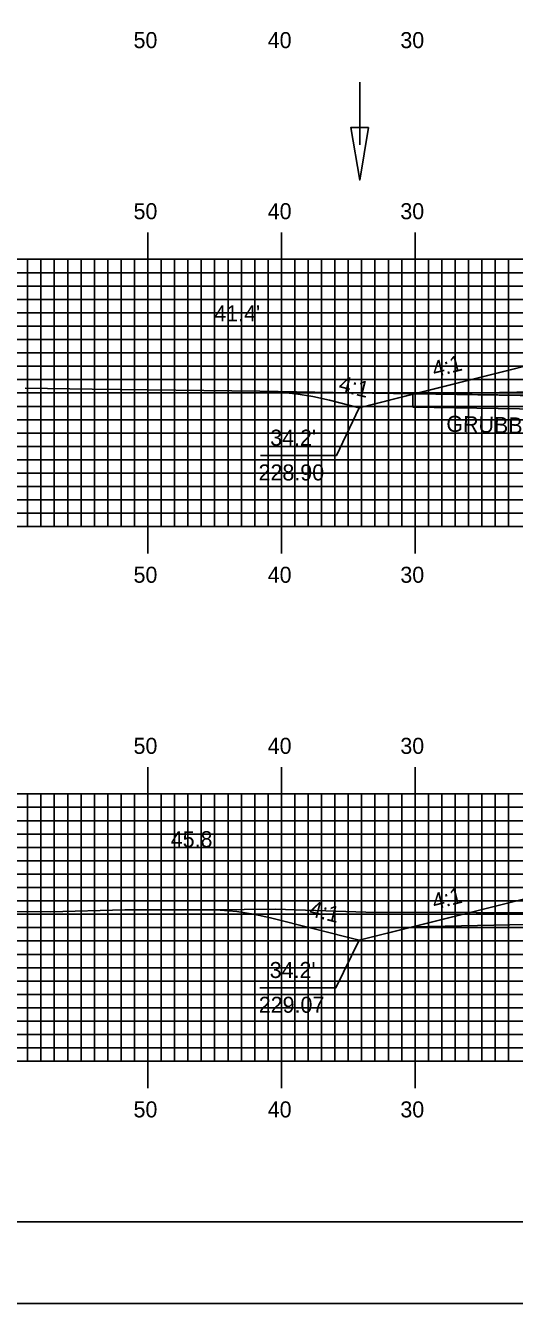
# Model space of a CAD drawing. Extents: x 1803503 to 1803847, y 442591 to 442811.
# Drawn here: x 1803610 to 1803646.6, y 442590.5 to 442686.2 of the extents above; entities that cross this region are included whole.
import ezdxf

# ---------------------------------------------------------------- set-up
doc = ezdxf.new("R2010")
doc.units = 0
for name, color, linetype in [('ANNOTATION', 7, 'Continuous'), ('BORDER', 7, 'Continuous'), ('D_Drainage_Ditch_Line', 7, 'Continuous'), ('D_Roadway_Centerline', 7, 'Continuous'), ('D_Roadway_SlopeLines', 7, 'Continuous'), ('D_Roadway_SubGrade', 7, 'Continuous'), ('D_Text_Standard', 7, 'Continuous'), ('GRUBBING IN FILL', 7, 'Continuous'), ('H_V ANNOTATION', 7, 'Continuous'), ('MAJOR', 7, 'Continuous'), ('MINOR', 7, 'Continuous'), ('PLOT BOUNDARY', 7, 'Continuous'), ('S_Roadway_Centerline', 7, 'Continuous')]:
    doc.layers.add(name, color=color, linetype=linetype)

msp = doc.modelspace()

# ---------------------------------------------------------------- linework, layer by layer
at = {"layer": 'ANNOTATION'}
for points in [[(1803627.565, 442653.994), (1803633.257, 442653.994), (1803634.967, 442657.564)], [(1803627.526, 442614.167), (1803633.218, 442614.167), (1803634.967, 442617.734)]]:
    msp.add_lwpolyline(points, dxfattribs=at)
at = {"layer": 'BORDER'}
msp.add_lwpolyline([(1803519.541, 442596.665), (1803839.541, 442596.665), (1803839.541, 442806.665), (1803519.541, 442806.665)], close=True, dxfattribs=at)
at = {"layer": 'D_Drainage_Ditch_Line'}
msp.add_line((1803634.995, 442677.222), (1803634.995, 442681.921), dxfattribs=at)
msp.add_lwpolyline([(1803635.651, 442678.535), (1803634.339, 442678.535), (1803634.995, 442674.598)], close=True, dxfattribs=at)
at = {"layer": 'D_Roadway_Centerline'}
for points in [[(1803627.728, 442658.786), (1803628.978, 442658.731), (1803630.228, 442658.602), (1803631.478, 442658.4), (1803632.728, 442658.124), (1803634.967, 442657.564), (1803638.967, 442658.564), (1803649.141, 442661.108), (1803657.141, 442661.428), (1803669.141, 442661.668), (1803681.141, 442661.775), (1803689.141, 442661.455), (1803699.315, 442658.912), (1803703.03, 442657.983)], [(1803623.31, 442620.005), (1803624.56, 442619.974), (1803625.81, 442619.862), (1803627.06, 442619.67), (1803628.31, 442619.398), (1803634.967, 442617.734), (1803638.967, 442618.734), (1803649.141, 442621.278), (1803657.141, 442621.598), (1803669.141, 442621.838), (1803681.141, 442621.71), (1803689.141, 442621.39), (1803699.315, 442618.846), (1803703.315, 442617.846), (1803707.321, 442618.848), (1803708.571, 442619.11), (1803709.821, 442619.272), (1803711.071, 442619.333), (1803712.321, 442619.293)]]:
    msp.add_lwpolyline(points, dxfattribs=at)
at = {"layer": 'D_Roadway_SlopeLines'}
for points in [[(1803649.141, 442661.108), (1803634.967, 442657.564)], [(1803634.967, 442657.564), (1803632.728, 442658.124), (1803631.478, 442658.4), (1803630.228, 442658.602), (1803628.978, 442658.731), (1803627.728, 442658.786)], [(1803649.141, 442621.278), (1803634.967, 442617.734)], [(1803634.967, 442617.734), (1803628.31, 442619.398), (1803627.06, 442619.67), (1803625.81, 442619.862), (1803624.56, 442619.974), (1803623.31, 442620.005)]]:
    msp.add_lwpolyline(points, dxfattribs=at)
at = {"layer": 'D_Roadway_SubGrade'}
for points in [[(1803657.141, 442658.928), (1803638.967, 442658.564), (1803649.141, 442661.108), (1803649.141, 442660.858), (1803657.141, 442661.178), (1803669.141, 442661.418), (1803681.141, 442661.525), (1803689.141, 442661.205), (1803689.141, 442661.455), (1803699.315, 442658.912), (1803681.141, 442659.275), (1803669.141, 442659.168)], [(1803657.141, 442619.097), (1803638.967, 442618.734), (1803649.141, 442621.278), (1803649.141, 442621.028), (1803657.141, 442621.348), (1803669.141, 442621.588), (1803681.141, 442621.46), (1803689.141, 442621.14), (1803689.141, 442621.39), (1803699.315, 442618.846), (1803681.141, 442619.21), (1803669.141, 442619.337)]]:
    msp.add_lwpolyline(points, close=True, dxfattribs=at)
at = {"layer": 'GRUBBING IN FILL'}
msp.add_line((1803638.967, 442658.564), (1803638.967, 442657.613), dxfattribs=at)
msp.add_line((1803638.967, 442658.564), (1803638.967, 442657.613), dxfattribs=at)
msp.add_lwpolyline([(1803638.967, 442657.613), (1803638.967, 442658.564), (1803640.322, 442658.591), (1803641.483, 442658.573), (1803653.042, 442658.437), (1803659.575, 442658.377), (1803664.893, 442658.416), (1803669.141, 442658.327), (1803669.141, 442657.326), (1803664.886, 442657.416), (1803659.574, 442657.377), (1803653.035, 442657.437), (1803648.563, 442657.458), (1803643.765, 442657.536)], close=True, dxfattribs=at)
msp.add_lwpolyline([(1803638.967, 442657.613), (1803638.967, 442658.564), (1803640.322, 442658.591), (1803641.483, 442658.573), (1803653.042, 442658.437), (1803659.575, 442658.377), (1803664.893, 442658.416), (1803669.141, 442658.327), (1803669.141, 442657.326), (1803664.886, 442657.416), (1803659.574, 442657.377), (1803653.035, 442657.437), (1803648.563, 442657.458), (1803643.765, 442657.536)], close=True, dxfattribs=at)
msp.add_lwpolyline([(1803638.967, 442657.613), (1803648.563, 442657.458), (1803653.035, 442657.437), (1803659.574, 442657.377), (1803664.886, 442657.416), (1803669.352, 442657.322), (1803674.258, 442657.391), (1803683.471, 442657.472), (1803685.85, 442657.406), (1803691.21, 442657.435), (1803693.562, 442657.442), (1803693.594, 442657.445), (1803695.278, 442657.365), (1803699.315, 442657.165)], dxfattribs=at)
msp.add_lwpolyline([(1803638.967, 442657.613), (1803648.563, 442657.458), (1803653.035, 442657.437), (1803659.574, 442657.377), (1803664.886, 442657.416), (1803669.352, 442657.322), (1803674.258, 442657.391), (1803683.471, 442657.472), (1803685.85, 442657.406), (1803691.21, 442657.435), (1803693.562, 442657.442), (1803693.594, 442657.445), (1803695.278, 442657.365), (1803699.315, 442657.165)], dxfattribs=at)
at = {"layer": 'MAJOR'}
for p, q in [((1803619.141, 442670.669), (1803619.141, 442668.665)), ((1803629.141, 442670.669), (1803629.141, 442668.665)), ((1803639.141, 442670.669), (1803639.141, 442668.665)), ((1803529.141, 442668.665), (1803809.141, 442668.665)), ((1803529.141, 442668.665), (1803809.141, 442668.665)), ((1803619.141, 442648.665), (1803619.141, 442668.665)), ((1803629.141, 442648.665), (1803629.141, 442668.665)), ((1803639.141, 442648.665), (1803639.141, 442668.665)), ((1803529.141, 442663.665), (1803809.141, 442663.665)), ((1803529.141, 442658.665), (1803809.141, 442658.665)), ((1803529.141, 442653.665), (1803809.141, 442653.665)), ((1803529.141, 442648.665), (1803809.141, 442648.665)), ((1803529.141, 442648.665), (1803809.141, 442648.665)), ((1803619.141, 442646.661), (1803619.141, 442648.665)), ((1803629.141, 442646.661), (1803629.141, 442648.665)), ((1803639.141, 442646.661), (1803639.141, 442648.665)), ((1803619.141, 442630.669), (1803619.141, 442628.665)), ((1803629.141, 442630.669), (1803629.141, 442628.665)), ((1803639.141, 442630.669), (1803639.141, 442628.665)), ((1803529.141, 442628.665), (1803809.141, 442628.665)), ((1803529.141, 442628.665), (1803809.141, 442628.665)), ((1803619.141, 442608.665), (1803619.141, 442628.665)), ((1803629.141, 442608.665), (1803629.141, 442628.665)), ((1803639.141, 442608.665), (1803639.141, 442628.665)), ((1803529.141, 442623.665), (1803809.141, 442623.665)), ((1803529.141, 442618.665), (1803809.141, 442618.665)), ((1803529.141, 442613.665), (1803809.141, 442613.665)), ((1803529.141, 442608.665), (1803809.141, 442608.665)), ((1803529.141, 442608.665), (1803809.141, 442608.665)), ((1803619.141, 442606.661), (1803619.141, 442608.665)), ((1803629.141, 442606.661), (1803629.141, 442608.665)), ((1803639.141, 442606.661), (1803639.141, 442608.665))]:
    msp.add_line(p, q, dxfattribs=at)
at = {"layer": 'MINOR'}
for p, q in [((1803610.141, 442648.665), (1803610.141, 442668.665)), ((1803611.141, 442648.665), (1803611.141, 442668.665)), ((1803612.141, 442648.665), (1803612.141, 442668.665)), ((1803613.141, 442648.665), (1803613.141, 442668.665)), ((1803614.141, 442648.665), (1803614.141, 442668.665)), ((1803615.141, 442648.665), (1803615.141, 442668.665)), ((1803616.141, 442648.665), (1803616.141, 442668.665)), ((1803617.141, 442648.665), (1803617.141, 442668.665)), ((1803618.141, 442648.665), (1803618.141, 442668.665)), ((1803620.141, 442648.665), (1803620.141, 442668.665)), ((1803621.141, 442648.665), (1803621.141, 442668.665)), ((1803622.141, 442648.665), (1803622.141, 442668.665)), ((1803623.141, 442648.665), (1803623.141, 442668.665)), ((1803624.141, 442648.665), (1803624.141, 442668.665)), ((1803625.141, 442648.665), (1803625.141, 442668.665)), ((1803626.141, 442648.665), (1803626.141, 442668.665)), ((1803627.141, 442648.665), (1803627.141, 442668.665)), ((1803628.141, 442648.665), (1803628.141, 442668.665)), ((1803630.141, 442648.665), (1803630.141, 442668.665)), ((1803631.141, 442648.665), (1803631.141, 442668.665)), ((1803632.141, 442648.665), (1803632.141, 442668.665)), ((1803633.141, 442648.665), (1803633.141, 442668.665)), ((1803634.141, 442648.665), (1803634.141, 442668.665)), ((1803635.141, 442648.665), (1803635.141, 442668.665)), ((1803636.141, 442648.665), (1803636.141, 442668.665)), ((1803637.141, 442648.665), (1803637.141, 442668.665)), ((1803638.141, 442648.665), (1803638.141, 442668.665)), ((1803640.141, 442648.665), (1803640.141, 442668.665)), ((1803641.141, 442648.665), (1803641.141, 442668.665)), ((1803642.141, 442648.665), (1803642.141, 442668.665)), ((1803643.141, 442648.665), (1803643.141, 442668.665)), ((1803644.141, 442648.665), (1803644.141, 442668.665)), ((1803645.141, 442648.665), (1803645.141, 442668.665)), ((1803646.141, 442648.665), (1803646.141, 442668.665)), ((1803529.141, 442667.665), (1803809.141, 442667.665)), ((1803529.141, 442666.665), (1803809.141, 442666.665)), ((1803529.141, 442665.665), (1803809.141, 442665.665)), ((1803529.141, 442664.665), (1803809.141, 442664.665)), ((1803529.141, 442662.665), (1803809.141, 442662.665)), ((1803529.141, 442661.665), (1803809.141, 442661.665)), ((1803529.141, 442660.665), (1803809.141, 442660.665)), ((1803529.141, 442659.665), (1803809.141, 442659.665)), ((1803529.141, 442657.665), (1803809.141, 442657.665)), ((1803529.141, 442656.665), (1803809.141, 442656.665)), ((1803529.141, 442655.665), (1803809.141, 442655.665)), ((1803529.141, 442654.665), (1803809.141, 442654.665)), ((1803529.141, 442652.665), (1803809.141, 442652.665)), ((1803529.141, 442651.665), (1803809.141, 442651.665)), ((1803529.141, 442650.665), (1803809.141, 442650.665)), ((1803529.141, 442649.665), (1803809.141, 442649.665)), ((1803610.141, 442608.665), (1803610.141, 442628.665)), ((1803611.141, 442608.665), (1803611.141, 442628.665)), ((1803612.141, 442608.665), (1803612.141, 442628.665)), ((1803613.141, 442608.665), (1803613.141, 442628.665)), ((1803614.141, 442608.665), (1803614.141, 442628.665)), ((1803615.141, 442608.665), (1803615.141, 442628.665)), ((1803616.141, 442608.665), (1803616.141, 442628.665)), ((1803617.141, 442608.665), (1803617.141, 442628.665)), ((1803618.141, 442608.665), (1803618.141, 442628.665)), ((1803620.141, 442608.665), (1803620.141, 442628.665)), ((1803621.141, 442608.665), (1803621.141, 442628.665)), ((1803622.141, 442608.665), (1803622.141, 442628.665)), ((1803623.141, 442608.665), (1803623.141, 442628.665)), ((1803624.141, 442608.665), (1803624.141, 442628.665)), ((1803625.141, 442608.665), (1803625.141, 442628.665)), ((1803626.141, 442608.665), (1803626.141, 442628.665)), ((1803627.141, 442608.665), (1803627.141, 442628.665)), ((1803628.141, 442608.665), (1803628.141, 442628.665)), ((1803630.141, 442608.665), (1803630.141, 442628.665)), ((1803631.141, 442608.665), (1803631.141, 442628.665)), ((1803632.141, 442608.665), (1803632.141, 442628.665)), ((1803633.141, 442608.665), (1803633.141, 442628.665)), ((1803634.141, 442608.665), (1803634.141, 442628.665)), ((1803635.141, 442608.665), (1803635.141, 442628.665)), ((1803636.141, 442608.665), (1803636.141, 442628.665)), ((1803637.141, 442608.665), (1803637.141, 442628.665)), ((1803638.141, 442608.665), (1803638.141, 442628.665)), ((1803640.141, 442608.665), (1803640.141, 442628.665)), ((1803641.141, 442608.665), (1803641.141, 442628.665)), ((1803642.141, 442608.665), (1803642.141, 442628.665)), ((1803643.141, 442608.665), (1803643.141, 442628.665)), ((1803644.141, 442608.665), (1803644.141, 442628.665)), ((1803645.141, 442608.665), (1803645.141, 442628.665)), ((1803646.141, 442608.665), (1803646.141, 442628.665)), ((1803529.141, 442627.665), (1803809.141, 442627.665)), ((1803529.141, 442626.665), (1803809.141, 442626.665)), ((1803529.141, 442625.665), (1803809.141, 442625.665)), ((1803529.141, 442624.665), (1803809.141, 442624.665)), ((1803529.141, 442622.665), (1803809.141, 442622.665)), ((1803529.141, 442621.665), (1803809.141, 442621.665)), ((1803529.141, 442620.665), (1803809.141, 442620.665)), ((1803529.141, 442619.665), (1803809.141, 442619.665)), ((1803529.141, 442617.665), (1803809.141, 442617.665)), ((1803529.141, 442616.665), (1803809.141, 442616.665)), ((1803529.141, 442615.665), (1803809.141, 442615.665)), ((1803529.141, 442614.665), (1803809.141, 442614.665)), ((1803529.141, 442612.665), (1803809.141, 442612.665)), ((1803529.141, 442611.665), (1803809.141, 442611.665)), ((1803529.141, 442610.665), (1803809.141, 442610.665)), ((1803529.141, 442609.665), (1803809.141, 442609.665))]:
    msp.add_line(p, q, dxfattribs=at)
at = {"layer": 'PLOT BOUNDARY'}
msp.add_lwpolyline([(1803503.354, 442590.547), (1803843.354, 442590.547), (1803843.354, 442810.547), (1803503.354, 442810.547)], close=True, dxfattribs=at)
at = {"layer": 'S_Roadway_Centerline'}
for points in [[(1803609.949, 442659.029), (1803614.977, 442658.948), (1803627.512, 442658.789), (1803634.393, 442658.687), (1803648.573, 442658.458), (1803653.042, 442658.437), (1803659.575, 442658.377), (1803664.893, 442658.416), (1803669.356, 442658.322), (1803674.246, 442658.391), (1803683.48, 442658.473), (1803685.861, 442658.406), (1803691.206, 442658.435), (1803693.521, 442658.442), (1803693.577, 442658.447), (1803695.327, 442658.364), (1803704.268, 442657.922), (1803710.833, 442657.578), (1803714.077, 442657.484), (1803724.068, 442657.305)], [(1803606.544, 442619.896), (1803611.858, 442619.837), (1803617.407, 442619.986), (1803624.006, 442620.007), (1803628.692, 442620.049), (1803635.445, 442619.815), (1803643.711, 442619.794), (1803647.236, 442619.774), (1803650.385, 442619.753), (1803669.868, 442618.924), (1803670.993, 442618.896), (1803676.847, 442619.119), (1803692.567, 442619.692), (1803694.128, 442619.723), (1803694.819, 442619.763), (1803698.458, 442619.507), (1803698.802, 442619.539), (1803703.061, 442619.604), (1803705.219, 442619.608), (1803707.043, 442619.737), (1803707.607, 442619.632), (1803714.277, 442619.152), (1803721.289, 442618.626)]]:
    msp.add_lwpolyline(points, dxfattribs=at)

# ---------------------------------------------------------------- texts
at = {"layer": 'ANNOTATION'}
for rotation, p in [(14.03624, (1803640.59, 442659.831)), (345.96376, (1803633.353, 442658.829)), (14.03624, (1803640.59, 442620.001)), (345.96376, (1803631.144, 442619.551))]:
    msp.add_text('4:1', height=1.2, rotation=rotation, dxfattribs=at).set_placement(p)
for s, p in [("34.2'", (1803628.3, 442654.72)), ('228.90', (1803627.427, 442652.12)), ("34.2'", (1803628.261, 442614.894)), ('229.07', (1803627.442, 442612.294))]:
    msp.add_text(s, height=1.2, dxfattribs=at).set_placement(p)
at = {"layer": 'D_Text_Standard'}
for s, p in [("41.4'", (1803624.112, 442664.02)), ("45.8'", (1803620.855, 442624.68))]:
    msp.add_text(s, height=1.2, dxfattribs=at).set_placement(p)
at = {"layer": 'GRUBBING IN FILL'}
msp.add_text('GRUBBING IN FILL', height=1.2, rotation=358.55884, dxfattribs=at).set_placement((1803641.468, 442655.77))
at = {"layer": 'H_V ANNOTATION'}
for s, p in [('50', (1803618.07, 442684.465)), ('40', (1803628.113, 442684.465)), ('30', (1803638.038, 442684.465)), ('50', (1803618.07, 442671.665)), ('40', (1803628.113, 442671.665)), ('30', (1803638.038, 442671.665)), ('50', (1803618.07, 442644.465)), ('40', (1803628.113, 442644.465)), ('30', (1803638.038, 442644.465)), ('50', (1803618.07, 442631.665)), ('40', (1803628.113, 442631.665)), ('30', (1803638.038, 442631.665)), ('50', (1803618.07, 442604.465)), ('40', (1803628.113, 442604.465)), ('30', (1803638.038, 442604.465))]:
    msp.add_text(s, height=1.2, dxfattribs=at).set_placement(p)

doc.saveas('drawing.dxf')
